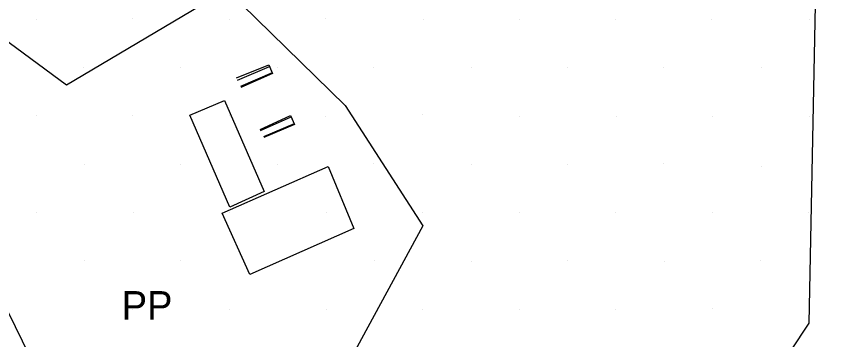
# Model space of a CAD drawing. Extents: x 1602514 to 1609837, y 863887 to 871157.
# Drawn here: x 1605427.6 to 1605605.2, y 866272.2 to 866343.2 of the extents above; entities that cross this region are included whole.
import ezdxf

# ---------------------------------------------------------------- set-up
doc = ezdxf.new("R2010")
doc.units = 0
for name, color, linetype in [('Survey-Buildings', 7, 'Continuous'), ('Survey-Private survey', 7, 'Continuous'), ('Survey-Ridge Lines', 7, 'Continuous'), ('Survey-Spot dirt', 7, 'Continuous'), ('Survey-Vegetation trees', 7, 'Continuous'), ('Survey-Walls', 7, 'Continuous'), ('Utility-Pole', 7, 'Continuous')]:
    doc.layers.add(name, color=color, linetype=linetype)

msp = doc.modelspace()

# ---------------------------------------------------------------- linework, layer by layer
at = {"layer": 'Survey-Buildings'}
msp.add_lwpolyline([(1605501.75, 866296.66), (1605478.92, 866286.58), (1605472.83, 866299.99), (1605496.15, 866310.23)], close=True, dxfattribs=at)
msp.add_lwpolyline([(1605501.75, 866296.66), (1605478.92, 866286.58), (1605472.83, 866299.99), (1605496.15, 866310.23)], close=True, dxfattribs=at)
at = {"layer": 'Survey-Private survey'}
msp.add_lwpolyline([(1605465.76, 866321.55), (1605473.32, 866324.72), (1605482.07, 866304.75), (1605474.54, 866301.31), (1605465.76, 866321.55)], dxfattribs=at)
msp.add_lwpolyline([(1605465.76, 866321.55), (1605473.32, 866324.72), (1605482.07, 866304.75), (1605474.54, 866301.31), (1605465.76, 866321.55)], dxfattribs=at)
at = {"layer": 'Survey-Ridge Lines'}
for points in [[(1605195.3, 866608.5), (1605255.31, 866523.97), (1605284.77, 866480.71), (1605316.58, 866443.2), (1605340.52, 866415.11), (1605363.23, 866384.67), (1605378.71, 866367.8), (1605403.27, 866330.55), (1605412.95, 866304.44), (1605430.55, 866268.66), (1605443.77, 866231.64), (1605454.66, 866201.21), (1605464.16, 866184.87), (1605467.92, 866182.17), (1605470.83, 866178.24), (1605475.29, 866169.59)], [(1605195.3, 866608.5), (1605255.31, 866523.97), (1605284.77, 866480.71), (1605316.58, 866443.2), (1605340.52, 866415.11), (1605363.23, 866384.67), (1605378.71, 866367.8), (1605403.27, 866330.55), (1605412.95, 866304.44), (1605430.55, 866268.66), (1605443.77, 866231.64), (1605454.66, 866201.21), (1605464.16, 866184.87), (1605467.92, 866182.17), (1605470.83, 866178.24), (1605475.29, 866169.59)], [(1605476.02, 866329.69), (1605483.07, 866332.54), (1605483.89, 866330.65), (1605476.97, 866327.61)], [(1605476.02, 866329.69), (1605483.07, 866332.54), (1605483.89, 866330.65), (1605476.97, 866327.61)], [(1605481.19, 866318.36), (1605487.85, 866321.43), (1605488.69, 866319.49), (1605481.99, 866316.61)], [(1605481.19, 866318.36), (1605487.85, 866321.43), (1605488.69, 866319.49), (1605481.99, 866316.61)]]:
    msp.add_lwpolyline(points, dxfattribs=at)
at = {"layer": 'Survey-Spot dirt'}
for p, q in [((1605432.08, 866342.57), (1605432.08, 866342.57)), ((1605432.08, 866342.57), (1605432.08, 866342.57)), ((1605453.1, 866342.72), (1605453.1, 866342.72)), ((1605453.1, 866342.72), (1605453.1, 866342.72)), ((1605474.45, 866342.52), (1605474.45, 866342.52)), ((1605474.45, 866342.52), (1605474.45, 866342.52)), ((1605495.5, 866342.77), (1605495.5, 866342.77)), ((1605495.5, 866342.77), (1605495.5, 866342.77)), ((1605516.96, 866342.49), (1605516.96, 866342.49)), ((1605516.96, 866342.49), (1605516.96, 866342.49)), ((1605538.09, 866342.51), (1605538.09, 866342.51)), ((1605538.09, 866342.51), (1605538.09, 866342.51)), ((1605559.31, 866342.53), (1605559.31, 866342.53)), ((1605559.31, 866342.53), (1605559.31, 866342.53)), ((1605580.37, 866342.62), (1605580.37, 866342.62)), ((1605580.37, 866342.62), (1605580.37, 866342.62)), ((1605601.74, 866342.52), (1605601.74, 866342.52)), ((1605601.74, 866342.52), (1605601.74, 866342.52)), ((1605442.43, 866331.96), (1605442.43, 866331.96)), ((1605442.43, 866331.96), (1605442.43, 866331.96)), ((1605463.77, 866331.95), (1605463.77, 866331.95)), ((1605463.77, 866331.95), (1605463.77, 866331.95)), ((1605485.09, 866332.01), (1605485.09, 866332.01)), ((1605485.09, 866332.01), (1605485.09, 866332.01)), ((1605506.14, 866332.01), (1605506.14, 866332.01)), ((1605506.14, 866332.01), (1605506.14, 866332.01)), ((1605527.7, 866331.96), (1605527.7, 866331.96)), ((1605527.7, 866331.96), (1605527.7, 866331.96)), ((1605548.68, 866331.94), (1605548.68, 866331.94)), ((1605548.68, 866331.94), (1605548.68, 866331.94)), ((1605569.79, 866332.03), (1605569.79, 866332.03)), ((1605569.79, 866332.03), (1605569.79, 866332.03)), ((1605591.21, 866331.9), (1605591.21, 866331.9)), ((1605591.21, 866331.9), (1605591.21, 866331.9)), ((1605431.98, 866321.41), (1605431.98, 866321.41)), ((1605431.98, 866321.41), (1605431.98, 866321.41)), ((1605453.2, 866321.38), (1605453.2, 866321.38)), ((1605453.2, 866321.38), (1605453.2, 866321.38)), ((1605474.39, 866321.34), (1605474.39, 866321.34)), ((1605474.39, 866321.34), (1605474.39, 866321.34)), ((1605495.64, 866321.3), (1605495.64, 866321.3)), ((1605495.64, 866321.3), (1605495.64, 866321.3)), ((1605516.91, 866321.74), (1605516.91, 866321.74)), ((1605516.91, 866321.74), (1605516.91, 866321.74)), ((1605538.17, 866321.26), (1605538.17, 866321.26)), ((1605538.17, 866321.26), (1605538.17, 866321.26)), ((1605559.45, 866321.19), (1605559.45, 866321.19)), ((1605559.45, 866321.19), (1605559.45, 866321.19)), ((1605580.57, 866321.32), (1605580.57, 866321.32)), ((1605580.57, 866321.32), (1605580.57, 866321.32)), ((1605601.75, 866321.19), (1605601.75, 866321.19)), ((1605601.75, 866321.19), (1605601.75, 866321.19)), ((1605442.62, 866310.68), (1605442.62, 866310.68)), ((1605442.62, 866310.68), (1605442.62, 866310.68)), ((1605463.77, 866310.75), (1605463.77, 866310.75)), ((1605463.77, 866310.75), (1605463.77, 866310.75)), ((1605485, 866310.67), (1605485, 866310.67)), ((1605485, 866310.67), (1605485, 866310.67)), ((1605506.18, 866310.83), (1605506.18, 866310.83)), ((1605506.18, 866310.83), (1605506.18, 866310.83)), ((1605527.66, 866310.7), (1605527.66, 866310.7)), ((1605527.66, 866310.7), (1605527.66, 866310.7)), ((1605548.66, 866310.61), (1605548.66, 866310.61)), ((1605548.66, 866310.61), (1605548.66, 866310.61)), ((1605569.77, 866310.92), (1605569.77, 866310.92)), ((1605569.77, 866310.92), (1605569.77, 866310.92)), ((1605591.25, 866310.29), (1605591.25, 866310.29)), ((1605591.25, 866310.29), (1605591.25, 866310.29)), ((1605431.96, 866300.16), (1605431.96, 866300.16)), ((1605431.96, 866300.16), (1605431.96, 866300.16)), ((1605453.31, 866300.06), (1605453.31, 866300.06)), ((1605453.31, 866300.06), (1605453.31, 866300.06)), ((1605474.39, 866300.09), (1605474.39, 866300.09)), ((1605474.39, 866300.09), (1605474.39, 866300.09)), ((1605495.66, 866300.14), (1605495.66, 866300.14)), ((1605495.66, 866300.14), (1605495.66, 866300.14)), ((1605516.86, 866300.19), (1605516.86, 866300.19)), ((1605516.86, 866300.19), (1605516.86, 866300.19)), ((1605538.08, 866300.16), (1605538.08, 866300.16)), ((1605538.08, 866300.16), (1605538.08, 866300.16)), ((1605559.25, 866300.2), (1605559.25, 866300.2)), ((1605559.25, 866300.2), (1605559.25, 866300.2)), ((1605580.53, 866300.08), (1605580.53, 866300.08)), ((1605580.53, 866300.08), (1605580.53, 866300.08)), ((1605601.7, 866300.14), (1605601.7, 866300.14)), ((1605601.7, 866300.14), (1605601.7, 866300.14)), ((1605442.62, 866289.53), (1605442.62, 866289.53)), ((1605442.62, 866289.53), (1605442.62, 866289.53)), ((1605463.78, 866289.52), (1605463.78, 866289.52)), ((1605463.78, 866289.52), (1605463.78, 866289.52)), ((1605485.15, 866289.16), (1605485.15, 866289.16)), ((1605485.15, 866289.16), (1605485.15, 866289.16)), ((1605506.33, 866289.56), (1605506.33, 866289.56)), ((1605506.33, 866289.56), (1605506.33, 866289.56)), ((1605527.49, 866289.34), (1605527.49, 866289.34)), ((1605527.49, 866289.34), (1605527.49, 866289.34)), ((1605548.68, 866289.54), (1605548.68, 866289.54)), ((1605548.68, 866289.54), (1605548.68, 866289.54)), ((1605569.95, 866289.46), (1605569.95, 866289.46)), ((1605569.95, 866289.46), (1605569.95, 866289.46)), ((1605591.16, 866289.54), (1605591.16, 866289.54)), ((1605591.16, 866289.54), (1605591.16, 866289.54)), ((1605453.16, 866278.91), (1605453.16, 866278.91)), ((1605453.16, 866278.91), (1605453.16, 866278.91)), ((1605474.38, 866278.97), (1605474.38, 866278.97)), ((1605474.38, 866278.97), (1605474.38, 866278.97)), ((1605495.66, 866278.89), (1605495.66, 866278.89)), ((1605495.66, 866278.89), (1605495.66, 866278.89)), ((1605516.83, 866278.88), (1605516.83, 866278.88)), ((1605516.83, 866278.88), (1605516.83, 866278.88)), ((1605538.12, 866278.95), (1605538.12, 866278.95)), ((1605538.12, 866278.95), (1605538.12, 866278.95)), ((1605559.31, 866278.85), (1605559.31, 866278.85)), ((1605559.31, 866278.85), (1605559.31, 866278.85)), ((1605580.46, 866279.01), (1605580.46, 866279.01)), ((1605580.46, 866279.01), (1605580.46, 866279.01)), ((1605601.66, 866278.96), (1605601.66, 866278.96)), ((1605601.66, 866278.96), (1605601.66, 866278.96))]:
    msp.add_line(p, q, dxfattribs=at)
at = {"layer": 'Survey-Vegetation trees'}
msp.add_lwpolyline([(1605384.81, 866367.9), (1605438.61, 866328.19), (1605473.87, 866349.1), (1605499.88, 866323.66), (1605516.94, 866297.2), (1605499.74, 866265.58), (1605531.83, 866253.13), (1605589.85, 866257.85), (1605601.79, 866275.83), (1605605.2, 866448.65)], dxfattribs=at)
msp.add_lwpolyline([(1605384.81, 866367.9), (1605438.61, 866328.19), (1605473.87, 866349.1), (1605499.88, 866323.66), (1605516.94, 866297.2), (1605499.74, 866265.58), (1605531.83, 866253.13), (1605589.85, 866257.85), (1605601.79, 866275.83), (1605605.2, 866448.65)], dxfattribs=at)
at = {"layer": 'Survey-Walls'}
for points in [[(1605476.23, 866329.23), (1605483.22, 866332.2), (1605483.83, 866330.78), (1605476.87, 866327.84)], [(1605476.23, 866329.23), (1605483.22, 866332.2), (1605483.83, 866330.78), (1605476.87, 866327.84)], [(1605481.28, 866318.18), (1605487.99, 866321.13), (1605488.63, 866319.62), (1605481.92, 866316.78)], [(1605481.28, 866318.18), (1605487.99, 866321.13), (1605488.63, 866319.62), (1605481.92, 866316.78)]]:
    msp.add_lwpolyline(points, dxfattribs=at)

# ---------------------------------------------------------------- texts
at = {"layer": 'Utility-Pole'}
msp.add_text('PP', height=6.251, dxfattribs=at).set_placement((1605450.77, 866276.65))
msp.add_text('PP', height=6.251, dxfattribs=at).set_placement((1605450.77, 866276.65))

doc.saveas('drawing.dxf')
